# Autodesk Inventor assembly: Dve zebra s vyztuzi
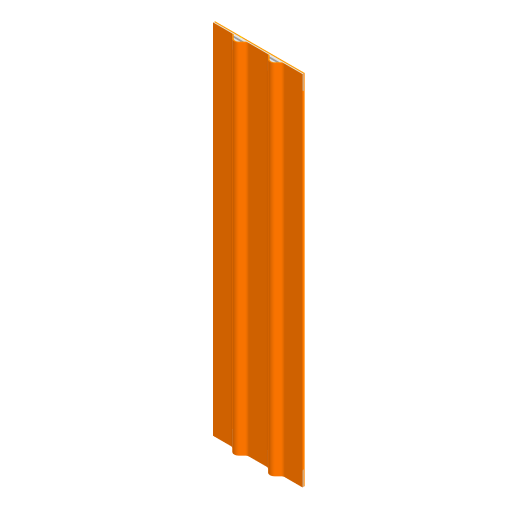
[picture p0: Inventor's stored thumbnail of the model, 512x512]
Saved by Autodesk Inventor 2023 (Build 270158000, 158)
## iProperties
Created: 2025-03
Part Number: Dve zebra s vyztuzi
Document SubType Name: Assembly
Designer: tomik
Author: tomik
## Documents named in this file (4)
- C:\Users\tomik\Desktop\Růčka_Tomáš_přílohy\Vyztužení\Dvě žebra s kanálky\Dve zebra_kanalek.iam
- C:\Users\tomik\Desktop\Růčka_Tomáš_přílohy\Vyztužení\Dvě žebra s kanálky\Spodni tkanina 50x200.ipt
- C:\Users\tomik\Desktop\Růčka_Tomáš_přílohy\Vyztužení\Dvě žebra s kanálky\Dve zebra s kanalkem.ipt
- C:\Users\tomik\Desktop\Růčka_Tomáš_přílohy\Vyztužení\Dvě žebra s kanálky\Horni tkanina.ipt
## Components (3 placed, 3 different names)
1. Spodni tkanina 50x200:1 — Proti sobě:1, Proti sobě:2, Stejný směr:1, Proti sobě:11, Proti sobě:13, Proti sobě:20, Proti sobě:21
2. Dve zebra s kanalkem:1 — Proti sobě:11, Proti sobě:13, Proti sobě:22
3. Horni tkanina:1 — Proti sobě:20, Proti sobě:21, Proti sobě:22
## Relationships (8: Mate 7, Flush 1)
- Proti sobě:1 [Mate]: Spodni tkanina 50x200:1
- Proti sobě:2 [Mate]: Spodni tkanina 50x200:1
- Stejný směr:1 [Flush]: Spodni tkanina 50x200:1
- Proti sobě:11 [Mate]: Spodni tkanina 50x200:1 ↔ Dve zebra s kanalkem:1
- Proti sobě:13 [Mate]: Spodni tkanina 50x200:1 ↔ Dve zebra s kanalkem:1
- Proti sobě:20 [Mate]: Spodni tkanina 50x200:1 ↔ Horni tkanina:1
- Proti sobě:21 [Mate]: Spodni tkanina 50x200:1 ↔ Horni tkanina:1
- Proti sobě:22 [Mate]: Dve zebra s kanalkem:1 ↔ Horni tkanina:1
